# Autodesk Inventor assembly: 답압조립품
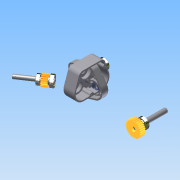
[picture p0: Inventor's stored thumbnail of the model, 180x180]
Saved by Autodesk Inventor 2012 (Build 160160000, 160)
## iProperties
Created: 2014-12
Part Number: 답압조립품
Document SubType Name: Assembly
Designer: Owner
Author: Owner
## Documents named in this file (13)
- C:\Documents and Settings\Owner\바탕 화면\441208V1023\답압조립품.iam
- C:\Documents and Settings\Owner\바탕 화면\441208V1023\본체.ipt
- C:\Documents and Settings\Owner\바탕 화면\441208V1023\서브축.ipt
- C:\Documents and Settings\Owner\바탕 화면\441208V1023\커버.ipt
- C:\Documents and Settings\Owner\바탕 화면\441208V1023\서브기어.ipt
- C:\Documents and Settings\Owner\바탕 화면\441208V1023\오일시일-D-15.ipt
- C:\Documents and Settings\Owner\바탕 화면\441208V1023\베어링- 6203.ipt
- C:\Documents and Settings\Owner\바탕 화면\441208V1023\키5x5.ipt
- C:\Documents and Settings\Owner\바탕 화면\441208V1023\베어링- 6202.ipt
- C:\Documents and Settings\Owner\바탕 화면\441208V1023\멈춤링.ipt
- C:\Documents and Settings\Owner\바탕 화면\441208V1023\오일시일-D-17.ipt
- C:\Documents and Settings\Owner\바탕 화면\441208V1023\메인축.ipt
- C:\Documents and Settings\Owner\바탕 화면\441208V1023\메인기어.ipt
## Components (12 placed, 5 different names)
1. KS B 2023 6203 - 17 x 40 x 12:1
2. KS B 2023 6203 - 17 x 40 x 12:2
3. KS B 2023 6202 - 15 x 35 x 11:1
4. KS B 2023 6202 - 15 x 35 x 11:2
5. KS B 1336 17 x 1:1
6. KS B 1336 17 x 1:2
7. KS B 2804 D D - 15 30 7:1
8. KS B 2804 D D - 15 30 7:2
9. KS B 2804 D D - 15 30 7:3
10. KS B 2804 D D - 15 30 7:4
11. KS B 2804 D D - 17 30 8:1
12. KS B 2023 6203 - 17 x 40 x 12:3
